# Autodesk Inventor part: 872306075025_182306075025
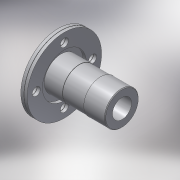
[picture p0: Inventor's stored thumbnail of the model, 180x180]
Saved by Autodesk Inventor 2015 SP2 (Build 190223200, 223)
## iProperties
Created: 2017-02
Part Number: 872306075025_182306075025
Material: PVC-Piping
Description: PLASSON FLANGE ADAPTOR WITH METAL FLANGE 75-2.1/2"
Document SubType Name: Modeling
Designer: KIM
Mass: 92.6774 g
Surface Area: 199.44 cm^2
Volume: 66.1981 cm^3
Density: 1.4 g/cm^3
Appearance: Smooth - White
Author: Кирилл
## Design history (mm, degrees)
derived "872306.ipt"
feature "Solid1::872306.ipt"
tag "TaggingFeature1"
body "Solid1"
other parameters: "d73" = 14.2, "d74" = 90 deg, "d75" = 0.3, "d76" = 185, "d77" = 18, "d78" = 72.5, "d80" = 0, "d82" = 360 deg, "d94" = 65, "d96" = 0.3, "d99" = 360 deg, "d101" = 75, "d103" = 142, "d104" = 1.5, "d107" = 97.5, "d108" = 3.55, "d116" = 73.5, "d117" = 47.33333, "d118" = 47.33333, "d119" = 75, "d120" = 3.75, "d_" = 75, "H_" = 142, "D_" = 185, "Dp_" = 145, "S_" = 18, "DN_" = 65
